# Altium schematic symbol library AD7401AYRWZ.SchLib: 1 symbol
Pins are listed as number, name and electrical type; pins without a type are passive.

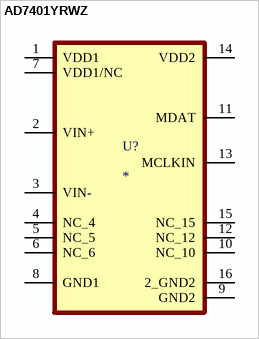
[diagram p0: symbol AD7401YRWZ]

## AD7401YRWZ
designator U?
Isolated Module 16 b Serial 16-SOIC; MF: Analog Devices; MP: AD7401YRWZ-REEL7
footprint AD7401AYRWZ
pins: 1 VDD1 (power), 2 VIN+, 3 VIN-, 4 NC_4, 5 NC_5, 6 NC_6, 7 VDD1/NC (power), 8 GND1, 9 GND2, 10 NC_10, 11 MDAT, 12 NC_12 (power), 13 MCLKIN, 14 VDD2 (power), 15 NC_15 (power), 16 2_GND2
